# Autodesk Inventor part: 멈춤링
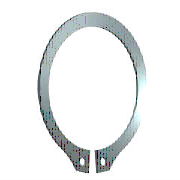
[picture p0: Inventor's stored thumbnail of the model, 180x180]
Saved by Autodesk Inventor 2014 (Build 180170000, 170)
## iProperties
IsCustomPart: 1
Company: 한국ATC센터
Created: 2014-10
Part Number: 멈춤링
Material: 강, 연강
Description: 리테이닝 링(C형)
Document SubType Name: Modeling
Standard: KS B 1336
Designer: 한국ATC센터
Standards Organization: KS
Language: ko-KR
Size Designation: 25 x 1.2
Categories: <MemberInstance><Categories><Category DisplayName="샤프트 부품" InternalName="7f7aeb1f-a693-4053-b835-cee3144e0d98" Mnemonic="SHFT"><Category DisplayName="써클립" Inter
Density: 7.86 g/cm^3
Mass: 2.3429 g
Surface Area: 7.2498 cm^2
Volume: 0.298079 cm^3
Appearance: 강철
Author: KYOUNG IL JANG
Revision Number: 1
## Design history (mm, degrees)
sketch "스케치1"
  geometry: L1 (-6, 0)-(6, 0) reference; L2 (0, 20.189)-(0, -80.536) reference; L3 (-48.09, 0)-(48.09, 0) reference; L4 (-0.5, -24.44)-(-0.5, -28.74); L5 (-0.5, -6.54)-(-0.5, -13.29); L6 (-2.795, 3.1)-(3.672, 3.1); L7 (0.5, -6.54)-(0.5, -13.29); L8 (0.5, -24.44)-(0.5, -28.74); C1 r 1 at (-2, -26.606); C2 r 1 at (2, -26.606); A1 r 11.95 centre (0, -12.5) between (0.5, -24.44) and (-0.5, -24.44); A2 r 14.825 centre (0, -11.725) between (5.202, -25.608) and (-5.202, -25.608); A3 r 16.247 centre (0, -12.5) between (-2.281, -28.586) and (-0.5, -28.74); A4 r 2 centre (-2, -26.606) between (-3.952, -27.043) and (-2.281, -28.586); A5 r 2 centre (-5.903, -27.48) between (-3.952, -27.043) and (-5.202, -25.608); A6 r 2 centre (5.903, -27.48) between (5.202, -25.608) and (3.952, -27.043); A7 r 2 centre (2, -26.606) between (2.281, -28.586) and (3.952, -27.043); A8 r 16.247 centre (0, -12.5) between (0.5, -28.74) and (2.281, -28.586)
  constraints: 16 point on circle, 12 end point, 10 centre point, 9 symmetric about line, 5 point on line, 4 tangent, 3 coincident, 2 horizontal, 1 perpendicular, 1 vertical, 5 other
  dimensions: "d0" = 23.9 diameter of A1 (= ND); "d1" = 4.3 distance of L4.end L4.start (= SRB2); "d6" = 0.5 distance between parallel lines of L2 L5 (= 0.25 x SD5); "d7" = 3.1 distance between parallel lines of L6 L3 (= SRB1); "d8" = 0.775 distance of A1.centre A2.centre (= 0.25 x SRB1); "d9" = 2 radius of A4 (= SD5); "d10" = 2 radius of A5 (= SD5); "d11" = 1.5 distance from line of L4 A4.centre (= 0.75 x SD5); "d12" = 2 diameter of C1 (= SD5); "d13" = 2 diameter of C2 (= SD5); "d14" = 12.5 distance from line of A1.centre L1 (= 0.5 x WD)
extrude "본체" new body sketch "스케치1" distance "d2" = 1.2 (= SD); taper "d3" = 0 deg
workaxis "Work Axis1"
workplane "Work Plane1"
body "Solid1"
other parameters: "WD" = 25 (= WDMIN) [user parameter; used in 1 equation term], "SD" = 1.2 [user parameter; used in 1 equation term], "SRB1" = 3.1 [user parameter; used in 2 equation terms], "ND" = 23.9 [user parameter; used in 1 equation term], "SRB2" = 4.3 [user parameter; used in 1 equation term], "SD5" = 2 [user parameter; used in 6 equation terms], "d15" = 0, "d16" = 0, "d17" = 0, "d41" = 0, "d42" = 0, "WDMIN" = 25 [user parameter; used in 1 equation term], "SD3" = 23.2 [user parameter], "WDMAX" = 26 [user parameter]
